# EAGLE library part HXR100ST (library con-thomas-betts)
THOMAS&BETTS
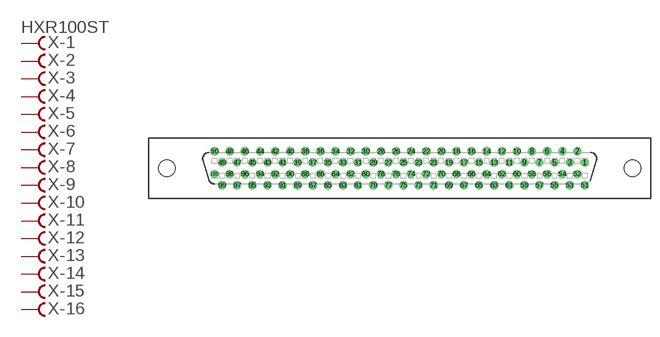
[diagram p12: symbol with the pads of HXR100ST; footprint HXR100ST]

Designator prefix X; gates -1=FV -2=F -3=F -4=F -5=F -6=F -7=F -8=F -9=F -10=F -11=F -12=F -13=F -14=F -15=F -16=F -17=F -18=F -19=F -20=F -21=F -22=F -23=F -24=F -25=F -26=F -27=F -28=F -29=F -30=F -31=F -32=F -33=F -34=F -35=F -36=F -37=F -38=F -39=F -40=F -41=F -42=F -43=F -44=F -45=F -46=F -47=F -48=F -49=F -50=F -51=F -52=F -53=F -54=F -55=F -56=F -57=F -58=F -59=F -60=F -61=F -62=F -63=F -64=F -65=F -66=F -67=F -68=F -69=F -70=F -71=F -72=F -73=F -74=F -75=F -76=F -77=F -78=F -79=F -80=F -81=F -82=F -83=F -84=F -85=F -86=F -87=F -88=F -89=F -90=F -91=F -92=F -93=F -94=F -95=F -96=F -97=F -98=F -99=F -100=F

## HXR100ST (OC_FARNELL: unknown; OC_NEWARK: unknown)  [HXR100ST]
1  -1:F  pas
2  -2:F  pas
3  -3:F  pas
4  -4:F  pas
5  -5:F  pas
6  -6:F  pas
7  -7:F  pas
8  -8:F  pas
9  -9:F  pas
10  -10:F  pas
11  -11:F  pas
12  -12:F  pas
13  -13:F  pas
14  -14:F  pas
15  -15:F  pas
16  -16:F  pas
17  -17:F  pas
18  -18:F  pas
19  -19:F  pas
20  -20:F  pas
21  -21:F  pas
22  -22:F  pas
23  -23:F  pas
24  -24:F  pas
25  -25:F  pas
26  -26:F  pas
27  -27:F  pas
28  -28:F  pas
29  -29:F  pas
30  -30:F  pas
31  -31:F  pas
32  -32:F  pas
33  -33:F  pas
34  -34:F  pas
35  -35:F  pas
36  -36:F  pas
37  -37:F  pas
38  -38:F  pas
39  -39:F  pas
40  -40:F  pas
41  -41:F  pas
42  -42:F  pas
43  -43:F  pas
44  -44:F  pas
45  -45:F  pas
46  -46:F  pas
47  -47:F  pas
48  -48:F  pas
49  -49:F  pas
50  -50:F  pas
51  -51:F  pas
52  -52:F  pas
53  -53:F  pas
54  -54:F  pas
55  -55:F  pas
56  -56:F  pas
57  -57:F  pas
58  -58:F  pas
59  -59:F  pas
60  -60:F  pas
61  -61:F  pas
62  -62:F  pas
63  -63:F  pas
64  -64:F  pas
65  -65:F  pas
66  -66:F  pas
67  -67:F  pas
68  -68:F  pas
69  -69:F  pas
70  -70:F  pas
71  -71:F  pas
72  -72:F  pas
73  -73:F  pas
74  -74:F  pas
75  -75:F  pas
76  -76:F  pas
77  -77:F  pas
78  -78:F  pas
79  -79:F  pas
80  -80:F  pas
81  -81:F  pas
82  -82:F  pas
83  -83:F  pas
84  -84:F  pas
85  -85:F  pas
86  -86:F  pas
87  -87:F  pas
88  -88:F  pas
89  -89:F  pas
90  -90:F  pas
91  -91:F  pas
92  -92:F  pas
93  -93:F  pas
94  -94:F  pas
95  -95:F  pas
96  -96:F  pas
97  -97:F  pas
98  -98:F  pas
99  -99:F  pas
100  -100:F  pas

## Footprint HXR100ST (pad centres in mm)
THOMAS&BETTS HFR100ST29xx, HFR100ST29xx
drill 0.864 octagon: 1 31.115,0.953
drill 0.864 round: 2 29.845,2.857; 3 28.575,0.953; 4 27.305,2.857; 5 26.035,0.953; 6 24.765,2.857; 7 23.495,0.953; 8 22.225,2.857; 9 20.955,0.953; 10 19.685,2.857; 11 18.415,0.953; 12 17.145,2.857; 13 15.875,0.953; 14 14.605,2.857; 15 13.335,0.953; 16 12.065,2.857; 17 10.795,0.953; 18 9.525,2.857; 19 8.255,0.953; 20 6.985,2.857; 21 5.715,0.953; 22 4.445,2.857; 23 3.175,0.953; 24 1.905,2.857; 25 0.635,0.953; 26 -0.635,2.857; 27 -1.905,0.953; 28 -3.175,2.857; 29 -4.445,0.953; 30 -5.715,2.857; 31 -6.985,0.953; 32 -8.255,2.857; 33 -9.525,0.953; 34 -10.795,2.857; 35 -12.065,0.953; 36 -13.335,2.857; 37 -14.605,0.953; 38 -15.875,2.857; 39 -17.145,0.953; 40 -18.415,2.857; 41 -19.685,0.953; 42 -20.955,2.857; 43 -22.225,0.953; 44 -23.495,2.857; 45 -24.765,0.953; 46 -26.035,2.857; 47 -27.305,0.953; 48 -28.575,2.857; 49 -29.845,0.953; 50 -31.115,2.857; 51 31.115,-2.857; 52 29.845,-0.953; 53 28.575,-2.857; 54 27.305,-0.953; 55 26.035,-2.857; 56 24.765,-0.953; 57 23.495,-2.857; 58 22.225,-0.953; 59 20.955,-2.857; 60 19.685,-0.953; 61 18.415,-2.857; 62 17.145,-0.953; 63 15.875,-2.857; 64 14.605,-0.953; 65 13.335,-2.857; 66 12.065,-0.953; 67 10.795,-2.857; 68 9.525,-0.953; 69 8.255,-2.857; 70 6.985,-0.953; 71 5.715,-2.857; 72 4.445,-0.953; 73 3.175,-2.857; 74 1.905,-0.953; 75 0.635,-2.857; 76 -0.635,-0.953; 77 -1.905,-2.857; 78 -3.175,-0.953; 79 -4.445,-2.857; 80 -5.715,-0.953; 81 -6.985,-2.857; 82 -8.255,-0.953; 83 -9.525,-2.857; 84 -10.795,-0.953; 85 -12.065,-2.857; 86 -13.335,-0.953; 87 -14.605,-2.857; 88 -15.875,-0.953; 89 -17.145,-2.857; 90 -18.415,-0.953; 91 -19.685,-2.857; 92 -20.955,-0.953; 93 -22.225,-2.857; 94 -23.495,-0.953; 95 -24.765,-2.857; 96 -26.035,-0.953; 97 -27.305,-2.857; 98 -28.575,-0.953; 99 -29.845,-2.857; 100 -31.115,-0.953
hole 2.769 at 39.116,0.013
hole 2.769 at -39.116,0.013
